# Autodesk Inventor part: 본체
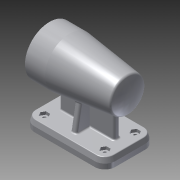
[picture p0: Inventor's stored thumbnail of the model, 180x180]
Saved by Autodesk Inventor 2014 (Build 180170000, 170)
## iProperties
Created: 2017-01
Part Number: 본체
Material: 알루미늄 6061
Document SubType Name: Modeling
Designer: owner
Density: 2.71 g/cm^3
Appearance: 알루미늄 - 평지
Mass: 794.538 g
Surface Area: 662.982 cm^2
Volume: 293.187 cm^3
Author: owner
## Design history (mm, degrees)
sketch "스케치1"
  geometry: L1 (-56, 35)-(56, 35); L2 (56, 35)-(56, -35); L3 (56, -35)-(-56, -35); L4 (-56, -35)-(-56, 35); 1 further point
  constraints: 8 end point, 2 parallel, 1 horizontal, 1 perpendicular
  dimensions: "d0" = 70 distance between parallel lines of L3 L1; "d1" = 112 distance between parallel lines of L4 L2; "d2" = 35 distance from line of point (0, 0) L1; "d3" = 56 distance from line of L2 point (0, 0)
extrude "돌출1" new body sketch "스케치1" distance "d4" = 7; taper "d5" = 0 deg
fillet "모깎기1" dims "d6" = 14
sketch "스케치2"
  geometry: L1 (-56, 0)-(-56, 7) reference; L2 (-56, 7)-(-42, 7) reference; L3 (56, 7)-(56, 0) reference; L4 (42, 7)-(56, 7) reference; L5 (-56, 7)-(-54.124, 14); L6 (-54.124, 14)-(54.124, 14); L7 (54.124, 14)-(56, 7); 1 further point
  constraints: 6 end point, 1 parallel
  dimensions: "d7" = 7 distance between parallel lines of L2 L6; "d8" = 15 deg angle of L1 L5; "d9" = 15 deg angle of L7 L3
sketch "스케치3"
  geometry: L1 (-56, 21)-(-56, -21) reference; L2 (-42, -35)-(42, -35) reference; L3 (56, -21)-(56, 21) reference; L4 (42, 35)-(-42, 35) reference; L5 (-54.124, -21)-(-54.124, 21); L6 (-42, 33.124)-(42, 33.124); L7 (54.124, 21)-(54.124, -21); L8 (42, -33.124)-(-42, -33.124); L9 (-54.124, 0)-(-56, 0) reference; L10 (-54.124, 0)-(-54.124, 5); A1 r 14 centre (-42, 21) between (-42, 35) and (-56, 21) reference; A2 r 14 centre (-42, -21) between (-56, -21) and (-42, -35) reference; A3 r 14 centre (42, -21) between (42, -35) and (56, -21) reference; A4 r 14 centre (42, 21) between (56, 21) and (42, 35) reference; A5 r 12.124 centre (-42, 21) between (-42, 33.124) and (-54.124, 21); A6 r 12.124 centre (42, 21) between (54.124, 21) and (42, 33.124); A7 r 12.124 centre (42, -21) between (42, -33.124) and (54.124, -21); A8 r 12.124 centre (-42, -21) between (-54.124, -21) and (-42, -33.124); 2 further points
  constraints: 10 end point, 8 point on circle, 4 centre point, 1 collinear, 1 perpendicular, 7 other
  dimensions: "d11" = 5 distance of L9.start L10.end
node "작업 평면1"
sketch "스케치4"
  geometry: L1 (12.124, 33.124)-(96.124, 33.124) reference; L2 (0, -21)-(0, 21) reference; L3 (96.124, -33.124)-(12.124, -33.124) reference; L4 (108.249, 21)-(108.249, -21) reference; L5 (96.124, 33.124)-(12.124, 33.124); L6 (0, 21)-(0, -21); L7 (12.124, -33.124)-(96.124, -33.124); L8 (108.249, -21)-(108.249, 21); A1 r 12.124 centre (12.124, 21) between (12.124, 33.124) and (0, 21) reference; A2 r 12.124 centre (12.124, -21) between (0, -21) and (12.124, -33.124) reference; A3 r 12.124 centre (96.124, -21) between (96.124, -33.124) and (108.249, -21) reference; A4 r 12.124 centre (96.124, 21) between (108.249, 21) and (96.124, 33.124) reference; A5 r 12.124 centre (12.124, 21) between (12.124, 33.124) and (0, 21); A6 r 12.124 centre (12.124, -21) between (0, -21) and (12.124, -33.124); A7 r 12.124 centre (96.124, -21) between (96.124, -33.124) and (108.249, -21); A8 r 12.124 centre (96.124, 21) between (108.249, 21) and (96.124, 33.124); 1 further point
  constraints: 8 end point, 8 point on circle, 4 centre point, 1 collinear, 7 other
sketch "스케치5"
  geometry: L1 (-56, 21)-(-56, -21) reference; L2 (-42, -35)-(42, -35) reference; L3 (56, -21)-(56, 21) reference; L4 (42, 35)-(-42, 35) reference; L5 (-56, 21)-(-56, -21); L6 (-42, -35)-(42, -35); L7 (56, -21)-(56, 21); L8 (42, 35)-(-42, 35); A1 r 14 centre (-42, 21) between (-42, 35) and (-56, 21) reference; A2 r 14 centre (-42, -21) between (-56, -21) and (-42, -35) reference; A3 r 14 centre (42, -21) between (42, -35) and (56, -21) reference; A4 r 14 centre (42, 21) between (56, 21) and (42, 35) reference; A5 r 14 centre (-42, 21) between (-42, 35) and (-56, 21); A6 r 14 centre (-42, -21) between (-56, -21) and (-42, -35); A7 r 14 centre (42, -21) between (42, -35) and (56, -21); A8 r 14 centre (42, 21) between (56, 21) and (42, 35); 1 further point
  constraints: 8 end point, 8 point on circle, 4 centre point, 1 collinear, 7 other
feature "로프트1" dims "d12" = 0, "d13" = 90 deg, "d14" = 0, "d15" = 90 deg
sketch "스케치6"
  geometry: L1 (42, 14)-(-42, 14) reference; L2 (-54.124, 14)-(-42, 14) reference; L3 (-56, 7)-(-54.124, 14) reference; L4 (-56, 0)-(-56, 7) reference; L5 (54.124, 14)-(56, 7) reference; L6 (42, 14)-(54.124, 14) reference; L7 (56, 7)-(56, 0) reference; L8 (-50, 74)-(59.367, 74); L9 (-42, 0)-(-56, 0) reference; L10 (56, 40)-(56, 53); L11 (56, 53)-(41, 53); L12 (41, 53)-(41, 53); L13 (38, 50)-(-10, 50); L14 (-13, 53)-(-13, 53); L15 (-13, 53)-(-25, 53); L16 (-25, 53)-(-25, 56.5); L17 (-25, 56.5)-(-43, 56.5); L18 (-43, 56.5)-(-43, 58); L19 (-43, 58)-(-47, 58); L20 (-47, 58)-(-47, 63.5); L21 (-47, 63.5)-(-50, 63.5); L22 (-50, 63.5)-(-50, 74); L23 (56, 40)-(28, 40); L24 (28, 40)-(-52.27, 49.856); L25 (-50, 74)-(-56, 74); L26 (56, 0)-(56, 7) reference; A1 r 80 centre (24, 74) between (-52.27, 49.856) and (-56, 74); A2 r 3 centre (38, 53) between (38, 50) and (41, 53); A3 r 3 centre (-10, 53) between (-13, 53) and (-10, 50); 1 further point
  constraints: 34 end point, 12 parallel, 6 point on circle, 4 perpendicular, 4 tangent, 3 centre point, 2 collinear, 1 equal radius, 1 point on line
  dimensions: "d16" = 74 distance between parallel lines of L9 L8; "d17" = 160 diameter of A1; "d18" = 15 distance between parallel lines of L12 L10; "d19" = 54 distance between parallel lines of L14 L12; "d20" = 12 distance between parallel lines of L16 L14; "d21" = 18 distance between parallel lines of L18 L16; "d22" = 4 distance between parallel lines of L20 L18; "d23" = 3 distance between parallel lines of L22 L20; "d24" = 7 deg angle of L8 L24; "d25" = 68 diameter of L23 L8; "d26" = 42 diameter of L11 L8; "d27" = 48 diameter of L13 L8; "d28" = 42 diameter of L15 L8; "d29" = 35 diameter of L17 L8; "d30" = 32 diameter of L19 L8; "d31" = 21 diameter of L21 L8; "d32" = 112 distance from line of L25.end L10; "d33" = 28 distance of L10.start L23.end; "d34" = 3 radius of A2
revolve "회전1" sketch "스케치6" stored, may be unused: angle "d35" = 90 deg
fillet "모깎기2" dims "d36" = 3
sketch "스케치7"
  geometry: L1 (28, 40)-(-50.331, 49.618) reference; L2 (42, 14)-(-42, 14) reference; L3 (-10, 50)-(38, 50) reference; L4 (38, 50)-(-38, 50); L5 (-38, 50)-(-38, 14); L6 (-38, 14)-(38, 14); L7 (38, 14)-(38, 50); L8 (-56, 0)-(-56, 7) reference; L9 (56, 7)-(56, 0) reference; 1 further point
  constraints: 8 end point, 2 parallel, 2 point on line, 1 horizontal, 1 perpendicular
  dimensions: "d37" = 18 distance from line of L8.start L5; "d38" = 18 distance between parallel lines of L9 L7
extrude "돌출2" join sketch "스케치7" stored distance "d39" = 8; taper "d40" = 0 deg
sketch "스케치8"
  geometry: L1 (21, 14)-(-21, 14) reference; L2 (-33.124, 14)-(-21, 14) reference; L3 (21, 14)-(33.124, 14) reference; L4 (-15.632, 55.789)-(-23, 14); L5 (-35, 0)-(-35, 7) reference; 2 further points
  constraints: 2 end point, 1 point on line, 2 other
  dimensions: "d41" = 12 distance from line of L5 L4.end; "d42" = 100 deg angle of L2 L4
feature "리브1" sketch "스케치8" dims "d43" = 1, "d44" = 8, "d45" = 0, "d46" = 0, "d47" = 1, "d48" = 1
sketch "스케치9"
  geometry: C1 r 21 at (0, 0) reference; 2 further points
  constraints: 1 horizontal alignment
  dimensions: "d49" = 26 distance of point (26, 0) C1.centre
hole "구멍1" sketch "스케치9" at (26, 0) diameter "d50" = 3.242; stored, may be unused: countersink angle "d54" = 90 deg, drill point angle "d56" = 118 deg; dims "d51" = 8, "d52" = 4, "d53" = 2, "d55" = 11
fillet "모깎기3" dims "d60" = 3
fillet "모깎기4" dims "d61" = 1
chamfer "모따기1" distance "d62" = 1; stored, may be unused: second distance "d63" = 2, angle "d64" = 45 deg
sketch "스케치10" dims "d65" = 10
  geometry: L1 (2.887, 6.357)-(-2.887, 6.357); L2 (-2.887, 6.357)-(-5.774, 11.357); L3 (-5.774, 11.357)-(-2.887, 16.357); L4 (-2.887, 16.357)-(2.887, 16.357); L5 (2.887, 16.357)-(5.774, 11.357); L6 (5.774, 11.357)-(2.887, 6.357); L7 (0, 11.357)-(0, 6.357); A1 r 11.357 centre (0, 11.357) between (-11.357, 11.357) and (0, 0) reference; 2 further points
  constraints: 14 end point, 2 coincident, 1 midpoint, 1 perpendicular, 1 vertical, 1 vertical alignment, 15 other
extrude "돌출3" cut sketch "스케치10" distance "d66" = 4; taper "d67" = 0 deg
sketch "스케치11"
  geometry: C1 r 2.5 at (0, 11.357); A1 r 11.357 centre (0, 11.357) between (-11.357, 11.357) and (0, 0) reference; 1 further point
  constraints: 1 centre point, 1 coincident
  dimensions: "d68" = 5 diameter of C1
extrude "돌출4" cut sketch "스케치11" distance "d69" = 100; taper "d70" = 0 deg
fillet "모깎기5" dims "d71" = 3
fillet "모깎기6" dims "d72" = 2
sketch "스케치13"
  geometry: L1 (0, 0)-(84, 0) reference; 3 further points
  constraints: 1 midpoint, 1 vertical alignment, 1 other
  dimensions: "d73" = 4 distance of point (42, 0) point (42, -4)
extrude "돌출5" join sketch "스케치13" distance "d74" = 0.5; taper "d75" = 0 deg
node "솔리드1"
mirror "대칭1"
pattern_circular "원형 패턴1" dims angle "d58" = 360 deg
mirror "대칭2"
mirror "대칭3"
